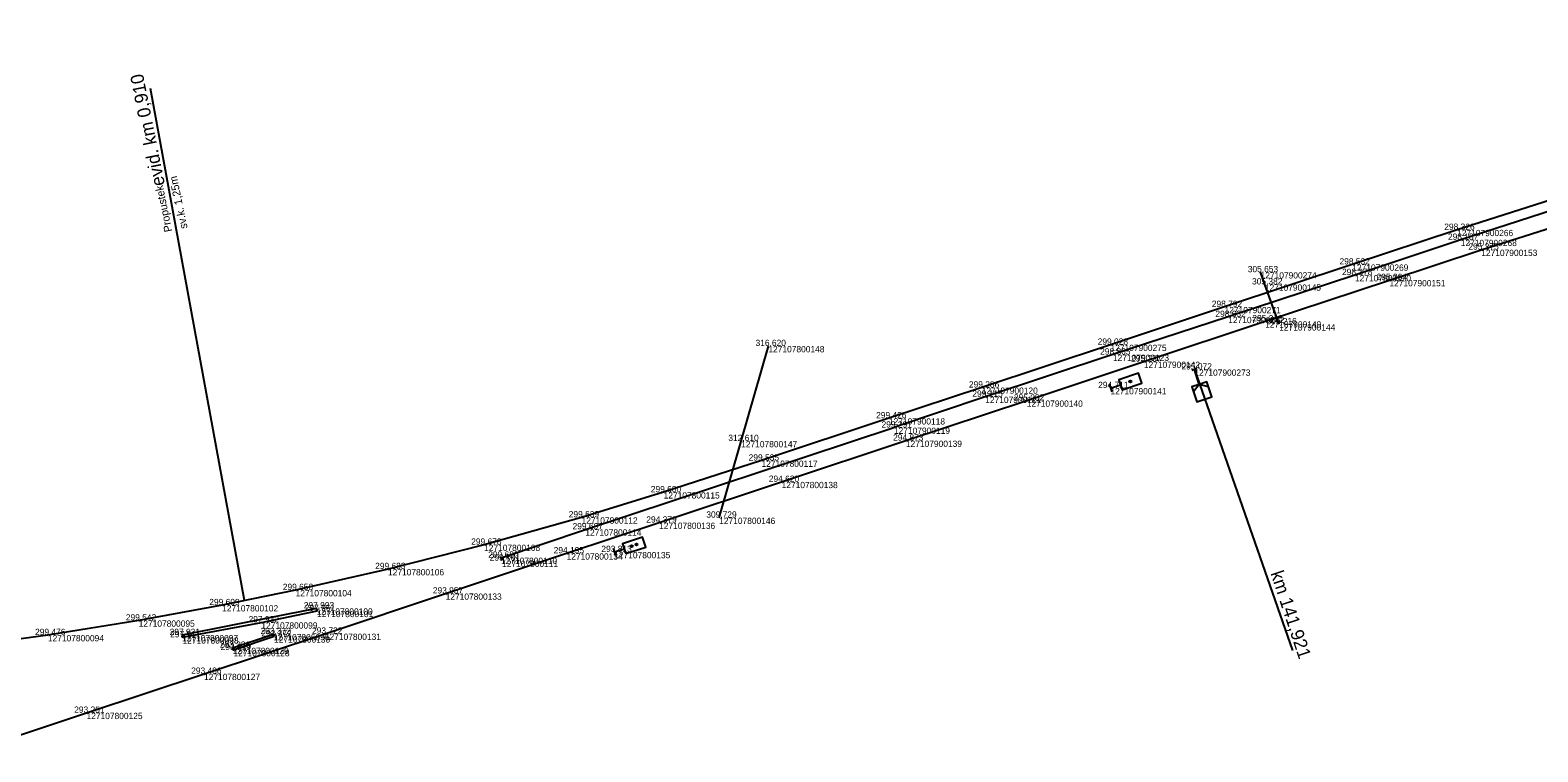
# Model space of a CAD drawing. Extents: x -616949 to -607976, y -1164436 to -1159224.
# Drawn here: x -608661.2 to -608373.2, y -1164435 to -1164297.1 of the extents above; entities that cross this region are included whole.
import ezdxf

# ---------------------------------------------------------------- set-up
doc = ezdxf.new("R2010")
doc.units = 0
for name, color, linetype in [('Vrstva 1', 7, 'Continuous'), ('Vrstva 13', 7, 'Continuous'), ('Vrstva 19', 7, 'Continuous'), ('Vrstva 25', 7, 'Continuous'), ('Vrstva 60', 7, 'Continuous'), ('Vrstva 61', 7, 'Continuous'), ('Vrstva 7', 7, 'Continuous')]:
    doc.layers.add(name, color=color, linetype=linetype)

msp = doc.modelspace()

# ---------------------------------------------------------------- linework, layer by layer
at = {"layer": 'Vrstva 1'}
for points in [[(-608370.66, -1164329.54), (-608388.63, -1164335.27), (-608408.65, -1164341.88), (-608433.05, -1164349.99), (-608454.84, -1164357.21), (-608479.44, -1164365.38), (-608497.16, -1164371.25), (-608521.5, -1164379.33), (-608540.2, -1164385.38), (-608555.88, -1164390.18), (-608574.5, -1164395.4), (-608592.85, -1164400.06), (-608610.5, -1164404.06), (-608624.54, -1164406.95), (-608640.48, -1164409.87), (-608657.82, -1164412.66), (-608673.15, -1164414.78)], [(-608672.87, -1164434.96), (-608650.44, -1164427.51), (-608628, -1164420.06), (-608604.91, -1164412.4), (-608581.84, -1164404.72), (-608558.74, -1164397.05), (-608541.06, -1164391.18), (-608517.66, -1164383.4), (-608493.92, -1164375.52), (-608470.84, -1164367.86), (-608448.46, -1164360.43), (-608425.29, -1164352.73), (-608401.56, -1164344.85), (-608384.02, -1164339.06), (-608368.83, -1164334.26)]]:
    msp.add_lwpolyline(points, dxfattribs=at)
at = {"layer": 'Vrstva 13'}
msp.add_line((-608555.15, -1164392.47), (-608496.21, -1164373.03), dxfattribs=at)
for points in [[(-608065.26, -1164300.03), (-608111.66, -1164297.85), (-608133.69, -1164297.22), (-608153.35, -1164297.13), (-608171.51, -1164297.5), (-608191.25, -1164298.49), (-608209.18, -1164299.8), (-608227.49, -1164301.64), (-608244.81, -1164303.74), (-608262.75, -1164306.4), (-608281.41, -1164309.57), (-608299.89, -1164313.12), (-608317.55, -1164317.08), (-608335.25, -1164321.42), (-608352.73, -1164326.21), (-608370.23, -1164331.44), (-608387.93, -1164337.17), (-608408.15, -1164343.91), (-608432.35, -1164351.89), (-608454.37, -1164359.09), (-608478.77, -1164367.14), (-608496.21, -1164373.03)], [(-608571.06, -1164398.45), (-608571.26, -1164397.88), (-608555.15, -1164392.47)]]:
    msp.add_lwpolyline(points, dxfattribs=at)
at = {"layer": 'Vrstva 19'}
for p, q in [((-608620.25, -1164406.07), (-608638.19, -1164308.3)), ((-608622.53, -1164415.09), (-608614.75, -1164412.48)), ((-608614.75, -1164412.48), (-608614.6, -1164412.91))]:
    msp.add_line(p, q, dxfattribs=at)
for points in [[(-608632.2, -1164412.66), (-608632.1, -1164413.09), (-608617.04, -1164410.23), (-608606.38, -1164408.04), (-608606.49, -1164407.56), (-608632.2, -1164412.66)], [(-608614.6, -1164412.91), (-608622.36, -1164415.52), (-608622.53, -1164415.09)]]:
    msp.add_lwpolyline(points, dxfattribs=at)
at = {"layer": 'Vrstva 25'}
for points in [[(-608422.61, -1164353.3), (-608425.35, -1164345.7), (-608426.17, -1164343.36)], [(-608529.59, -1164390.24), (-608525.39, -1164375.6), (-608520.19, -1164357.46)]]:
    msp.add_lwpolyline(points, dxfattribs=at)
at = {"layer": 'Vrstva 60'}
for p, q in [((-608388.63, -1164335.27), (-608388.63, -1164335.27)), ((-608387.93, -1164337.17), (-608387.93, -1164337.17)), ((-608384.02, -1164339.06), (-608384.02, -1164339.06)), ((-608408.65, -1164341.88), (-608408.65, -1164341.88)), ((-608426.17, -1164343.36), (-608426.17, -1164343.36)), ((-608425.35, -1164345.7), (-608425.35, -1164345.7)), ((-608408.15, -1164343.91), (-608408.15, -1164343.91)), ((-608401.56, -1164344.85), (-608401.56, -1164344.85)), ((-608433.05, -1164349.99), (-608433.05, -1164349.99)), ((-608432.35, -1164351.89), (-608432.35, -1164351.89)), ((-608425.29, -1164352.73), (-608425.29, -1164352.73)), ((-608422.61, -1164353.3), (-608422.61, -1164353.3)), ((-608520.19, -1164357.46), (-608520.19, -1164357.46)), ((-608454.84, -1164357.21), (-608454.84, -1164357.21)), ((-608454.37, -1164359.09), (-608454.37, -1164359.09)), ((-608448.46, -1164360.43), (-608448.46, -1164360.43)), ((-608438.82, -1164361.94), (-608438.82, -1164361.94)), ((-608479.44, -1164365.38), (-608479.44, -1164365.38)), ((-608454.85, -1164365.48), (-608454.85, -1164365.48)), ((-608478.77, -1164367.14), (-608478.77, -1164367.14)), ((-608470.84, -1164367.86), (-608470.84, -1164367.86)), ((-608497.16, -1164371.25), (-608497.16, -1164371.25)), ((-608496.21, -1164373.03), (-608496.21, -1164373.03)), ((-608525.39, -1164375.6), (-608525.39, -1164375.6)), ((-608493.92, -1164375.52), (-608493.92, -1164375.52)), ((-608521.5, -1164379.33), (-608521.5, -1164379.33)), ((-608517.66, -1164383.4), (-608517.66, -1164383.4)), ((-608540.2, -1164385.38), (-608540.2, -1164385.38)), ((-608555.88, -1164390.18), (-608555.88, -1164390.18)), ((-608541.06, -1164391.18), (-608541.06, -1164391.18)), ((-608529.59, -1164390.24), (-608529.59, -1164390.24)), ((-608555.15, -1164392.47), (-608555.15, -1164392.47)), ((-608574.5, -1164395.4), (-608574.5, -1164395.4)), ((-608558.74, -1164397.05), (-608558.74, -1164397.05)), ((-608549.64, -1164396.79), (-608549.64, -1164396.79)), ((-608592.85, -1164400.06), (-608592.85, -1164400.06)), ((-608571.26, -1164397.88), (-608571.26, -1164397.88)), ((-608571.06, -1164398.45), (-608571.06, -1164398.45)), ((-608610.5, -1164404.06), (-608610.5, -1164404.06)), ((-608581.84, -1164404.72), (-608581.84, -1164404.72)), ((-608624.54, -1164406.95), (-608624.54, -1164406.95)), ((-608606.49, -1164407.56), (-608606.49, -1164407.56)), ((-608606.38, -1164408.04), (-608606.38, -1164408.04)), ((-608640.48, -1164409.87), (-608640.48, -1164409.87)), ((-608617.04, -1164410.23), (-608617.04, -1164410.23)), ((-608657.82, -1164412.66), (-608657.82, -1164412.66)), ((-608632.2, -1164412.66), (-608632.2, -1164412.66)), ((-608632.1, -1164413.09), (-608632.1, -1164413.09)), ((-608622.53, -1164415.09), (-608622.53, -1164415.09)), ((-608614.75, -1164412.48), (-608614.75, -1164412.48)), ((-608614.6, -1164412.91), (-608614.6, -1164412.91)), ((-608604.91, -1164412.4), (-608604.91, -1164412.4)), ((-608622.36, -1164415.52), (-608622.36, -1164415.52)), ((-608628, -1164420.06), (-608628, -1164420.06)), ((-608650.44, -1164427.51), (-608650.44, -1164427.51))]:
    msp.add_line(p, q, dxfattribs=at)
at = {"layer": 'Vrstva 7'}
for p, q in [((-608438.35, -1164361.78), (-608439.3, -1164362.1)), ((-608437.88, -1164364.79), (-608438.82, -1164361.94)), ((-608438.82, -1164361.94), (-608420.08, -1164415.62)), ((-608455.08, -1164364.77), (-608454.61, -1164366.19)), ((-608450.87, -1164364.31), (-608451.23, -1164364.13)), ((-608549.87, -1164396.08), (-608549.4, -1164397.5)), ((-608546.13, -1164395.77), (-608546.49, -1164395.59)), ((-608545.19, -1164395.46), (-608545.54, -1164395.28))]:
    msp.add_line(p, q, dxfattribs=at)
for points in [[(-608454.85, -1164365.48), (-608452.95, -1164364.85), (-608452.63, -1164365.8), (-608448.84, -1164364.54), (-608449.47, -1164362.64), (-608453.26, -1164363.9), (-608452.95, -1164364.85)], [(-608437.88, -1164364.79), (-608439.3, -1164365.26), (-608438.35, -1164368.11), (-608435.51, -1164367.16), (-608436.45, -1164364.31), (-608437.88, -1164364.79)], [(-608436.14, -1164365.27), (-608437.88, -1164364.79), (-608438.98, -1164366.21)], [(-608549.64, -1164396.79), (-608547.74, -1164396.16), (-608547.42, -1164397.11), (-608543.63, -1164395.85), (-608544.26, -1164393.95), (-608548.05, -1164395.21), (-608547.74, -1164396.16)]]:
    msp.add_lwpolyline(points, dxfattribs=at)
for centre in [(-608451.05, -1164364.22), (-608546.31, -1164395.69), (-608545.37, -1164395.37)]:
    msp.add_circle(centre, 0.2, dxfattribs=at)

# ---------------------------------------------------------------- texts
at = {"layer": 'Vrstva 19'}
for s, height, rotation, p in [('evid. km 0,910', 2.5, 101.2139, (-608635.45, -1164326.65)), ('sv.k. 1,25m', 1.5, 101.6141, (-608631.13, -1164334.92)), ('Propustek', 1.5, 101.6141, (-608634.06, -1164335.52))]:
    msp.add_text(s, height=height, rotation=rotation, dxfattribs=at).set_placement(p)
at = {"layer": 'Vrstva 60'}
for s, p in [('127107900266', (-608388.63, -1164336.47)), ('127107900268', (-608387.93, -1164338.37)), ('127107900153', (-608384.02, -1164340.26)), ('127107900269', (-608408.65, -1164343.08)), ('127107900274', (-608426.17, -1164344.56)), ('127107900145', (-608425.35, -1164346.9)), ('127107900270', (-608408.15, -1164345.1)), ('127107900151', (-608401.56, -1164346.05)), ('127107900271', (-608433.05, -1164351.19)), ('127107900272', (-608432.35, -1164353.09)), ('127107900149', (-608425.29, -1164353.93)), ('127107900144', (-608422.61, -1164354.5)), ('127107800148', (-608520.19, -1164358.66)), ('127107900275', (-608454.84, -1164358.41)), ('127107900123', (-608454.37, -1164360.29)), ('127107900142', (-608448.46, -1164361.63)), ('127107900273', (-608438.82, -1164363.14)), ('127107900120', (-608479.44, -1164366.58)), ('127107900141', (-608454.85, -1164366.68)), ('127107900121', (-608478.77, -1164368.34)), ('127107900140', (-608470.84, -1164369.06)), ('127107900118', (-608497.16, -1164372.45)), ('127107900119', (-608496.21, -1164374.23)), ('127107800147', (-608525.39, -1164376.8)), ('127107900139', (-608493.92, -1164376.72)), ('127107800117', (-608521.5, -1164380.53)), ('127107800138', (-608517.66, -1164384.6)), ('127107800115', (-608540.2, -1164386.58)), ('127107800112', (-608555.88, -1164391.38)), ('127107800136', (-608541.06, -1164392.38)), ('127107800146', (-608529.59, -1164391.44)), ('127107800114', (-608555.15, -1164393.67)), ('127107800108', (-608574.5, -1164396.6)), ('127107800134', (-608558.74, -1164398.25)), ('127107800135', (-608549.64, -1164397.99)), ('127107800106', (-608592.85, -1164401.26)), ('127107800110', (-608571.26, -1164399.08)), ('127107800111', (-608571.06, -1164399.65)), ('127107800104', (-608610.5, -1164405.26)), ('127107800133', (-608581.84, -1164405.92)), ('127107800102', (-608624.54, -1164408.15)), ('127107800100', (-608606.49, -1164408.76)), ('127107800101', (-608606.38, -1164409.24)), ('127107800095', (-608640.48, -1164411.07)), ('127107800099', (-608617.04, -1164411.43)), ('127107800094', (-608657.82, -1164413.86)), ('127107800097', (-608632.2, -1164413.86)), ('127107800098', (-608632.1, -1164414.29)), ('127107800129', (-608622.53, -1164416.29)), ('127107806096', (-608614.75, -1164413.68)), ('127107800130', (-608614.6, -1164414.11)), ('127107800131', (-608604.91, -1164413.59)), ('127107800128', (-608622.36, -1164416.72)), ('127107800127', (-608628, -1164421.26)), ('127107800125', (-608650.44, -1164428.71))]:
    msp.add_text(s, height=1.2, dxfattribs=at).set_placement(p)
at = {"layer": 'Vrstva 61'}
for s, p in [('298.326', (-608391.08, -1164335.27)), ('298.187', (-608390.38, -1164337.17)), ('295.375', (-608386.48, -1164339.06)), ('305.653', (-608428.62, -1164343.36)), ('298.532', (-608411.1, -1164341.88)), ('298.378', (-608410.61, -1164343.91)), ('305.382', (-608427.8, -1164345.7)), ('295.364', (-608404.01, -1164344.85)), ('298.792', (-608435.49, -1164349.99)), ('298.632', (-608434.8, -1164351.89)), ('295.316', (-608427.74, -1164352.73)), ('305.216', (-608425.06, -1164353.3)), ('316.620', (-608522.64, -1164357.46)), ('299.028', (-608457.29, -1164357.21)), ('298.865', (-608456.82, -1164359.09)), ('295.237', (-608450.91, -1164360.43)), ('295.072', (-608441.27, -1164361.94)), ('299.286', (-608481.89, -1164365.38)), ('299.115', (-608481.23, -1164367.14)), ('294.711', (-608457.2, -1164365.48)), ('295.092', (-608473.29, -1164367.86)), ('299.426', (-608499.61, -1164371.25)), ('299.291', (-608498.57, -1164373.03)), ('312.610', (-608527.84, -1164375.6)), ('294.873', (-608496.37, -1164375.52)), ('299.535', (-608523.96, -1164379.33)), ('294.620', (-608520.11, -1164383.4)), ('299.600', (-608542.65, -1164385.38)), ('299.639', (-608558.33, -1164390.18)), ('309.729', (-608532.05, -1164390.24)), ('299.697', (-608557.6, -1164392.47)), ('294.379', (-608543.51, -1164391.18)), ('299.678', (-608576.96, -1164395.4)), ('299.680', (-608573.71, -1164397.88)), ('299.701', (-608573.42, -1164398.45)), ('294.195', (-608561.2, -1164397.05)), ('293.813', (-608552.09, -1164396.79)), ('299.683', (-608595.31, -1164400.06)), ('299.658', (-608612.95, -1164404.06)), ('293.957', (-608584.29, -1164404.72)), ('299.609', (-608626.99, -1164406.95)), ('297.993', (-608608.94, -1164407.56)), ('299.542', (-608642.93, -1164409.87)), ('297.932', (-608619.49, -1164410.23)), ('297.961', (-608608.74, -1164408.04)), ('299.476', (-608660.27, -1164412.66)), ('297.921', (-608634.56, -1164412.66)), ('297.911', (-608634.46, -1164413.09)), ('293.372', (-608617.2, -1164412.48)), ('293.372', (-608617.05, -1164412.91)), ('293.722', (-608607.36, -1164412.4)), ('293.286', (-608624.98, -1164415.09)), ('293.319', (-608624.82, -1164415.52)), ('293.486', (-608630.45, -1164420.06)), ('293.251', (-608652.8, -1164427.51))]:
    msp.add_text(s, height=1.2, dxfattribs=at).set_placement(p)
at = {"layer": 'Vrstva 7'}
msp.add_text('km 141,921', height=2.5, rotation=288.3689, dxfattribs=at).set_placement((-608424.31, -1164400.85))

doc.saveas('drawing.dxf')
